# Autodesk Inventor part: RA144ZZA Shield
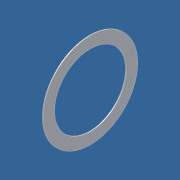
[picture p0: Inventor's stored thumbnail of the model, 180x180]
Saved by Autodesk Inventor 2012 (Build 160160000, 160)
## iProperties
Category: PARTsolutions
Created: 2011-07
Part Number: RA144ZZA Shield
Catalog Web Link: www.cadenas.de
Description: Six types s - Inch system sizes
Document SubType Name: Modeling
Designer: PARTsolutions
Density: 1 g/cm^3
Material: Par défaut
NB: RA144ZZA Shield
NN: Six types s
NT: Inch system sizes
NBSYN: RA144ZZA Shield
LINA: RA144ZZA Shield
SD: 3.175
D: 6.350
B: 2.380
B1: 2.779
D1: 7.52
D2: 7.52
C1: 0.58
C2: 0.79
R: 0.08
ORDER: RA144ZZA
CR: 284
COR: 96
CRF: 29
CORF: 10
LSG: 59000
LSO: 70000
MASS: 0.27
ORDER1: R144
WSS: RA144ZA
WDS: RA144ZZA
UTWF: FLR144
FORSS: FLRA144ZA
FORDS: FLRA144ZZA
DA1: 3.9
DA2: 4
DA: 5.5
RAS: 0.08
MASS1: 0.33
VERS: 3
X: 1.587
N: 9
O: 14.954
RB: 0.470
KT: DUMMY
SUPPLIER: NTN
ARTICLENO: RA144ZZA Shield
BOMINFO: RA144ZZA Shield
CREATOR: CADENAS GmbH
PSOL_IDENT_0: {\\10.0.0.251\ps_data\23d-libs\ntn\ball_roller_bearings\miniature_extra_small_bb\inch_system_sizes\i
PSOL_IDENT_1: ss_s.prj},180 {VTYP=3D},{NB=RA144ZZA Shield},{LINA=RA144ZZA Shield},{NN=Six types s},{DATE=11.12.200
PSOL_IDENT_2: 7 08:48:22},{GEOMDATE=02.04.2007 13:01:00},{VERSION=},{LINEID=16080},{LINESUBID=-1},{WBVAR=}  {NB=RA
PSOL_IDENT_3: 144ZZA Shield},{LINA=RA144ZZA Shield},{KT=DUMMY},{IDNR=},{SD=3.175},{D=6.350},{B=2.380},{B1=2.779},{
PSOL_IDENT_4: D1=7.52},{D2=7.52},{C1=0.58},{C2=0.79},{R=0.08},{ORDER=RA144ZZA},{CR=284},{COR=96},{CRF=29},{CORF=10
PSOL_IDENT_5: },{LSG=59000},{LSO=70000},{MASS=0.27},{ORDER1=R144},{WSS=RA144ZA},{WDS=RA144ZZA},{UTWF=FLR144},{FORS
PSOL_IDENT_6: S=FLRA144ZA},{FORDS=FLRA144ZZA},{DA1=3.9},{DA2=4},{DA=5.5},{RAS=0.08},{MASS1=0.33},{VERS=3},{X=1.587
PSOL_IDENT_7: 5},{N=9},{O=14.95425},{RB=0.4699}
Title: RA144ZZA Shield
Author: Cadenas PARTsolutions
Comments: Inch system sizes
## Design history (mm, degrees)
sketch "Sketch_1"
  geometry: L1 (-0.015, 0)-(-0.063, 0); L2 (-0.063, 2.096)-(-0.015, 2.096); L3 (-0.015, 2.096)-(-0.015, 2.769); L4 (-0.015, 2.769)-(-0.063, 2.769); L5 (-0.063, 2.769)-(-0.063, 2.096)
  constraints: 10 end point
revolve "Revolution1" sketch "Sketch_1" stored, may be unused: angle "d0" = 360 deg
node "iss_s_XY"
node "iss_s_YZ"
node "iss_s_ZX"
node "iss_s_X"
node "iss_s_Y"
node "iss_s_Z"
node "iss_s_Center"
node "Solide1"
node "Corps solides"
node "Corps surfaciques"
